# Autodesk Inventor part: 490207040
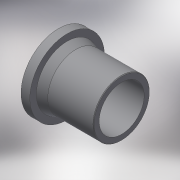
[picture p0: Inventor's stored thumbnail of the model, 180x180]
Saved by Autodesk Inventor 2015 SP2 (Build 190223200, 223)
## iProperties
Created: 2017-07
Part Number: 490207040
Material: Generic
Description: Stub Flange 40
Document SubType Name: Modeling
Designer: Кирилл
Mass: 81.8286 g
Surface Area: 283.894 cm^2
Volume: 81.8286 cm^3
Density: 1 g/cm^3
Appearance: Default
Author: Кирилл
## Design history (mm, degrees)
derived "490207.ipt"
feature "Solid1::490207.ipt"
tag "TaggingFeature1"
body "Solid1"
other parameters: "d0" = 85, "d3" = 32, "d4" = 78, "d5" = 11, "d17" = 0.8, "d18" = 0.8, "d19" = 0.8, "d21" = 0.8, "d24" = 0.8, "d25" = 0.8, "d26" = 0.4, "d27" = 0, "d32" = 0.4, "L_" = 85, "D_" = 78, "a_" = 11
